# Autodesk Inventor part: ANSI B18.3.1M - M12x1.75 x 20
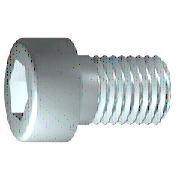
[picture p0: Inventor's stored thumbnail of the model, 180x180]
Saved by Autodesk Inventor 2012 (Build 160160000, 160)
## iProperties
Created: 2011-02
Part Number: ANSI B18.3.1M - M12x1.75 x 20
Material: Steel, Mild
Description: Broached Socket Head Cap Screw - Metric
Document SubType Name: Modeling
Standard: ANSI B18.3.1M
Designer: jrr70267
Standard Revision: 1979
Standards Organization: ANSI
Language: en-US
Size Designation: M12x1.75 x 20
Categories: <MemberInstance><Categories><Category DisplayName="Fasteners" InternalName="e4da775c-781d-43d5-af7c-5136215cf5a6" Mnemonic="FSTN"><Category DisplayName="Bolts"
Density: 1 g/cm^3
IsCustomPart: 0
Author: jrr70267
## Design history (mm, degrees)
workplane "Work Plane1"
revolve "Body" stored, may be unused: angle "d10" = 90 deg
sketch "Sketch2"
  geometry: L1 (0, -12.6)-(0, 12.6) reference; L2 (-12.6, 0)-(12.6, 0) reference; L3 (5.774, 0)-(2.887, -5); L4 (2.887, -5)-(-2.887, -5); L5 (-2.887, -5)-(-5.774, 0); L6 (-5.774, 0)-(-2.887, 5); L7 (-2.887, 5)-(2.887, 5); L8 (2.887, 5)-(5.774, 0); 2 further points
  constraints: 12 end point, 1 coincident, 1 horizontal alignment, 1 point on line, 12 other
extrude "Slot" join sketch "Sketch2" taper "d9" = 0 deg; stored distance "d11" = 10
body "Solid1"
fillet "Fillet2" dims "d16" = 1.2 (= RR)
feature "Thread" dims "d12" = 16.65292 (= GEL), "d13" = 0
chamfer "Chamfer1" distance "d14" = 1.07354 (= -0.5 x SPD + 0.5 x GD); stored, may be unused: second distance "d15" = 1.07354 (= GUL), angle "d27" = 45 deg
fillet "Fillet1" dims "d29" = 0.6 (= R)
sketch "Sketch1"
  geometry: L1 (-2.667, 0)-(20, 0); L2 (20, 0)-(20, 6); L3 (20, 6)-(3.347, 6); L4 (3.347, 6)-(2.274, 6); L5 (2.274, 6)-(0, 6); L6 (0, 6)-(0, 9); L7 (0, 9)-(-12, 9); L8 (-12, 9)-(-12, 5.774); L9 (-12, 5.774)-(-6, 5.774); L10 (-6, 5.774)-(-2.667, 0); L11 (-18.4, 0)-(26.4, 0) reference; L12 (0, -1.8)-(0, 10.8) reference; L13 (3.347, 6)-(0, 6)
  constraints: 22 end point, 6 parallel, 3 collinear, 1 horizontal, 1 perpendicular, 1 point on line
  dimensions: "d0" = 16.65292 distance from line of L3.end L2 (= GEL); "d1" = 1.07354 distance of L4.end L3.end (= GAL); "d2" = 12 distance between parallel lines of L8 L6 (= KOH); "d3" = 6 distance of L8.end L9.end (= INTI); "d4" = 60 deg angle of L10 L1; "d5" = 12 diameter of L3 L1 (= GD); "d6" = 12 diameter of L5 L1 (= BDM); "d7" = 11.54701 diameter of L9 L1 (= 1.1547 x SW); "d8" = 18 diameter of L7 L1 (= KOD); "d19" = 20 distance between parallel lines of L2 L6 (= NLG)
other parameters: "GD" = 12 (= NND) [user parameter; used in 2 equation terms], "NLG" = 20 [user parameter; used in 1 equation term], "GEL" = 16.65292 [user parameter; used in 2 equation terms], "KOD" = 18 [user parameter; used in 2 equation terms], "KOH" = 12 [user parameter; used in 1 equation term], "INTI" = 6 [user parameter; used in 1 equation term], "GAL" = 1.07354 (= 0.61345 x PTC) [user parameter; used in 1 equation term], "GUL" = 1.07354 (= 0.61345 x PTC) [user parameter; used in 1 equation term], "BDM" = 12 (= NND) [user parameter; used in 1 equation term], "RR" = 1.2 [user parameter; used in 1 equation term], "SPD" = 9.85293 [user parameter; used in 1 equation term], "d17" = 0, "d18" = 0, "d28" = 0.6 (= R), "R" = 0.6 [user parameter; used in 2 equation terms], "TOA" = 30 deg [user parameter], "THREADDIA" = 12 [user parameter; used in 1 equation term], "KOD1" = 18 (= KOD) [user parameter], "TPU" = 5.71429 (computed from PTC) [user parameter], "PTC" = 1.75 [user parameter; used in 4 equation terms], "NND" = 12 [user parameter; used in 2 equation terms], "E0" = 11.55 (= 1.155 x SW) [user parameter], "GD1" = 9.85293 (= THREADDIA - 1.2269 x PTC) [user parameter]
